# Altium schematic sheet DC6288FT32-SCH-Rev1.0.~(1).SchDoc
size A4
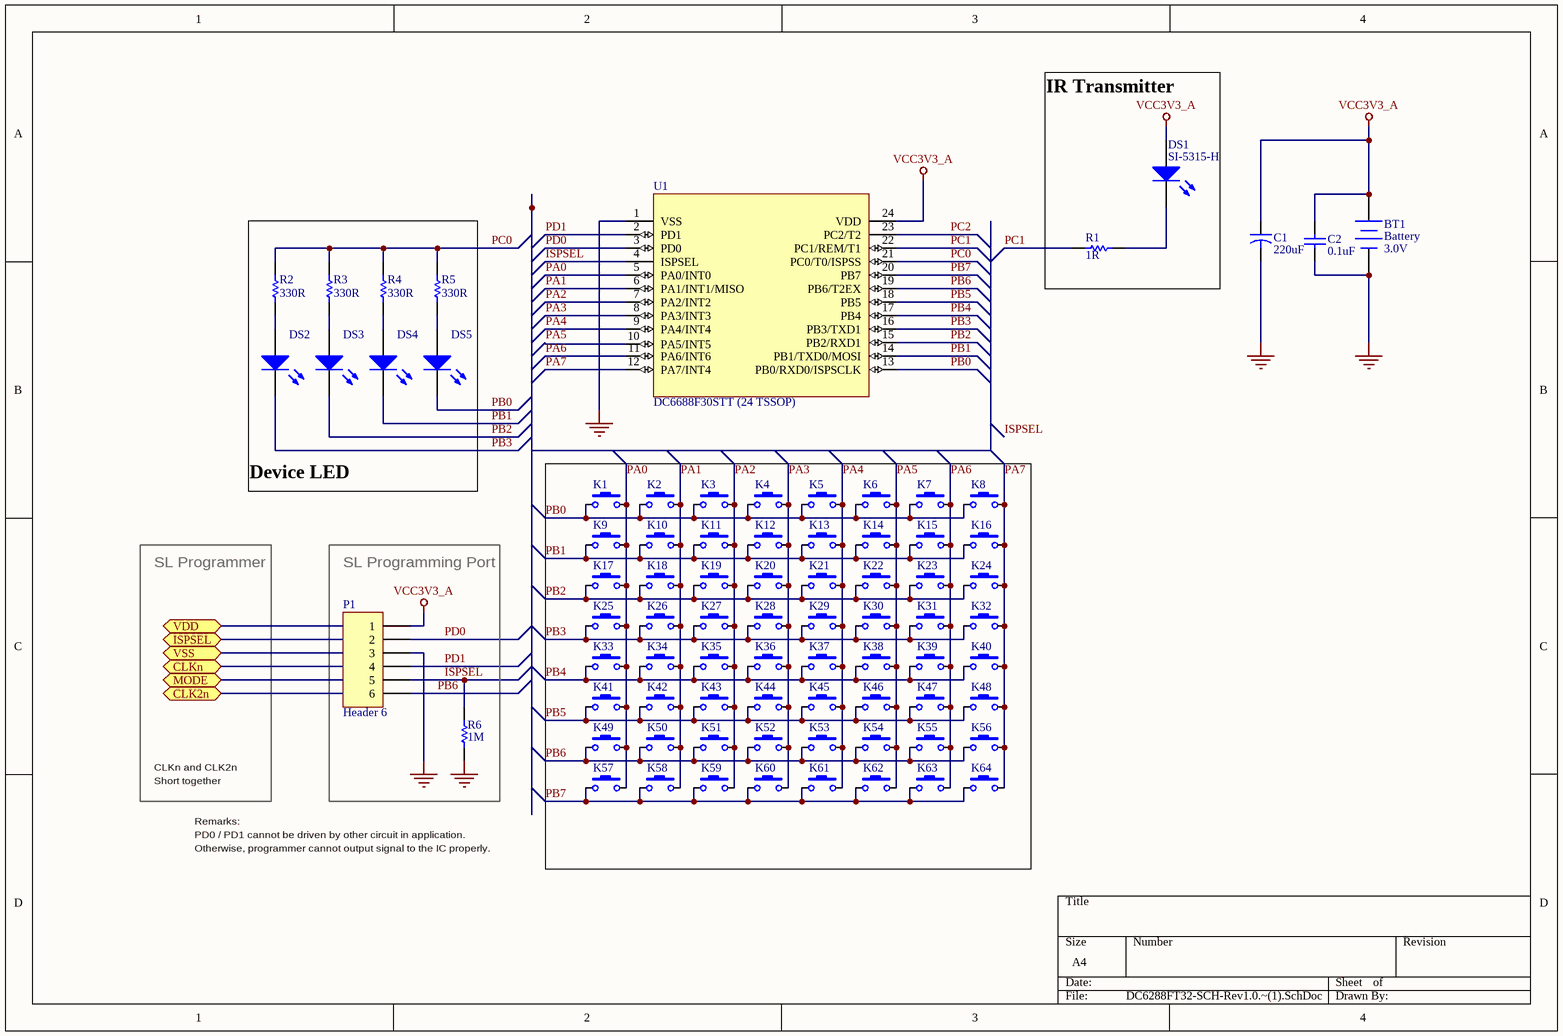
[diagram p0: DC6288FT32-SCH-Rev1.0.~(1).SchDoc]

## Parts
BT1  Battery  value 3.0V  [BAT-2]
C1  value 220uF  [CAPR5-4X5]  (hidden comment: Cap2)
C2  value 0.1uF  [RAD-0.3]  (hidden comment: Cap)
DS1  SPEC: SI-5315-H  [LED-0]  (hidden comment: LED0)
DS2  LED1  [LED-1]  (value not drawn)
DS3  LED1  [LED-1]  (value not drawn)
DS4  LED1  [LED-1]  (value not drawn)
DS5  LED1  [LED-1]  (value not drawn)
K1  KEYPAD_SW  [DPST-4]  (value not drawn)
K2  KEYPAD_SW  [DPST-4]  (value not drawn)
K3  KEYPAD_SW  [DPST-4]  (value not drawn)
K4  KEYPAD_SW  [DPST-4]  (value not drawn)
K5  KEYPAD_SW  [DPST-4]  (value not drawn)
K6  KEYPAD_SW  [DPST-4]  (value not drawn)
K7  KEYPAD_SW  [DPST-4]  (value not drawn)
K8  KEYPAD_SW  [DPST-4]  (value not drawn)
K9  KEYPAD_SW  [DPST-4]  (value not drawn)
K10  KEYPAD_SW  [DPST-4]  (value not drawn)
K11  KEYPAD_SW  [DPST-4]  (value not drawn)
K12  KEYPAD_SW  [DPST-4]  (value not drawn)
K13  KEYPAD_SW  [DPST-4]  (value not drawn)
K14  KEYPAD_SW  [DPST-4]  (value not drawn)
K15  KEYPAD_SW  [DPST-4]  (value not drawn)
K16  KEYPAD_SW  [DPST-4]  (value not drawn)
K17  KEYPAD_SW  [DPST-4]  (value not drawn)
K18  KEYPAD_SW  [DPST-4]  (value not drawn)
K19  KEYPAD_SW  [DPST-4]  (value not drawn)
K20  KEYPAD_SW  [DPST-4]  (value not drawn)
K21  KEYPAD_SW  [DPST-4]  (value not drawn)
K22  KEYPAD_SW  [DPST-4]  (value not drawn)
K23  KEYPAD_SW  [DPST-4]  (value not drawn)
K24  KEYPAD_SW  [DPST-4]  (value not drawn)
K25  KEYPAD_SW  [DPST-4]  (value not drawn)
K26  KEYPAD_SW  [DPST-4]  (value not drawn)
K27  KEYPAD_SW  [DPST-4]  (value not drawn)
K28  KEYPAD_SW  [DPST-4]  (value not drawn)
K29  KEYPAD_SW  [DPST-4]  (value not drawn)
K30  KEYPAD_SW  [DPST-4]  (value not drawn)
K31  KEYPAD_SW  [DPST-4]  (value not drawn)
K32  KEYPAD_SW  [DPST-4]  (value not drawn)
K33  KEYPAD_SW  [DPST-4]  (value not drawn)
K34  KEYPAD_SW  [DPST-4]  (value not drawn)
K35  KEYPAD_SW  [DPST-4]  (value not drawn)
K36  KEYPAD_SW  [DPST-4]  (value not drawn)
K37  KEYPAD_SW  [DPST-4]  (value not drawn)
K38  KEYPAD_SW  [DPST-4]  (value not drawn)
K39  KEYPAD_SW  [DPST-4]  (value not drawn)
K40  KEYPAD_SW  [DPST-4]  (value not drawn)
K41  KEYPAD_SW  [DPST-4]  (value not drawn)
K42  KEYPAD_SW  [DPST-4]  (value not drawn)
K43  KEYPAD_SW  [DPST-4]  (value not drawn)
K44  KEYPAD_SW  [DPST-4]  (value not drawn)
K45  KEYPAD_SW  [DPST-4]  (value not drawn)
K46  KEYPAD_SW  [DPST-4]  (value not drawn)
K47  KEYPAD_SW  [DPST-4]  (value not drawn)
K48  KEYPAD_SW  [DPST-4]  (value not drawn)
K49  KEYPAD_SW  [DPST-4]  (value not drawn)
K50  KEYPAD_SW  [DPST-4]  (value not drawn)
K51  KEYPAD_SW  [DPST-4]  (value not drawn)
K52  KEYPAD_SW  [DPST-4]  (value not drawn)
K53  KEYPAD_SW  [DPST-4]  (value not drawn)
K54  KEYPAD_SW  [DPST-4]  (value not drawn)
K55  KEYPAD_SW  [DPST-4]  (value not drawn)
K56  KEYPAD_SW  [DPST-4]  (value not drawn)
K57  KEYPAD_SW  [DPST-4]  (value not drawn)
K58  KEYPAD_SW  [DPST-4]  (value not drawn)
K59  KEYPAD_SW  [DPST-4]  (value not drawn)
K60  KEYPAD_SW  [DPST-4]  (value not drawn)
K61  KEYPAD_SW  [DPST-4]  (value not drawn)
K62  KEYPAD_SW  [DPST-4]  (value not drawn)
K63  KEYPAD_SW  [DPST-4]  (value not drawn)
K64  KEYPAD_SW  [DPST-4]  (value not drawn)
P1  Header 6  [HDR1X6]
R1  value 1R  [AXIAL-0.3]  (hidden comment: Res1)
R2  value 330R  [AXIAL-0.3]  (hidden comment: Res1)
R3  value 330R  [AXIAL-0.3]  (hidden comment: Res1)
R4  value 330R  [AXIAL-0.3]  (hidden comment: Res1)
R5  value 330R  [AXIAL-0.3]  (hidden comment: Res1)
R6  value 1M  [AXIAL-0.3]  (hidden comment: Res1)
U1  DC6688F30STT (24 TSSOP)

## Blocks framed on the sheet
SL Programming Port: P1 R6

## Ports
CLK2n, CLKn, ISPSEL, MODE, VDD, VSS

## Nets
GND: BT1.2(-) C1.2 C2.1 P1.3 R6.1 U1.1(VSS)
VCC3V3_A: BT1.1(+) C1.1 C2.2 DS1.1(A) P1.1 U1.24(VDD)
ISPSEL: P1.5 R6.2 U1.4(ISPSEL)
PA0: K1.2 K9.2 K17.2 K25.2 K33.2 K41.2 K49.2 K57.2 U1.5(PA0/INT0)
PA1: K2.2 K10.2 K18.2 K26.2 K34.2 K42.2 K50.2 K58.2 U1.6(PA1/INT1/MISO)
PA2: K3.2 K11.2 K19.2 K27.2 K35.2 K43.2 K51.2 K59.2 U1.7(PA2/INT2)
PA3: K4.2 K12.2 K20.2 K28.2 K36.2 K44.2 K52.2 K60.2 U1.8(PA3/INT3)
PA4: K5.2 K13.2 K21.2 K29.2 K37.2 K45.2 K53.2 K61.2 U1.9(PA4/INT4)
PA5: K6.2 K14.2 K22.2 K30.2 K38.2 K46.2 K54.2 K62.2
PA6: K7.2 K15.2 K23.2 K31.2 K39.2 K47.2 K55.2 K63.2 U1.11(PA6/INT6)
PA7: K8.2 K16.2 K24.2 K32.2 K40.2 K48.2 K56.2 K64.2 U1.12(PA7/INT4)
PB0: DS5.2(K) K1.1 K2.1 K3.1 K4.1 K5.1 K6.1 K7.1 K8.1 U1.13(PB0/RXD0/ISPSCLK)
PB1: DS4.2(K) K9.1 K10.1 K11.1 K12.1 K13.1 K14.1 K15.1 K16.1 U1.14(PB1/TXD0/MOSI)
PB2: DS3.2(K) K17.1 K18.1 K19.1 K20.1 K21.1 K22.1 K23.1 K24.1 U1.15(PB2/RXD1)
PB3: DS2.2(K) K25.1 K26.1 K27.1 K28.1 K29.1 K30.1 K31.1 K32.1 U1.16(PB3/TXD1)
PB4: K33.1 K34.1 K35.1 K36.1 K37.1 K38.1 K39.1 K40.1 U1.17(PB4)
PB5: K41.1 K42.1 K43.1 K44.1 K45.1 K46.1 K47.1 K48.1 U1.18(PB5)
PB6: K49.1 K50.1 K51.1 K52.1 K53.1 K54.1 K55.1 K56.1 P1.6 U1.19(PB6/T2EX)
PB7: K57.1 K58.1 K59.1 K60.1 K61.1 K62.1 K63.1 K64.1 U1.20(PB7)
PC0: R2.2 R3.2 R4.2 R5.2 U1.21(PC0/T0/ISPSS)
PC1: R1.1 U1.22(PC1/REM/T1)
PC2: U1.23(PC2/T2)
PD0: P1.2 U1.3(PD0)
PD1: P1.4 U1.2(PD1)
NetDS1_2: DS1.2(K) R1.2
NetDS2_1: DS2.1(A) R2.1
NetDS3_1: DS3.1(A) R3.1
NetDS4_1: DS4.1(A) R4.1
NetDS5_1: DS5.1(A) R5.1

Not connected (* = marked no-connect by the designer): U1 10(PA5/INT5)

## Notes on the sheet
- IR Transmitter
- Device LED
- SL Programmer
- CLKn and CLK2n
- Short together
- Remarks:
- PD0 / PD1 cannot be driven by other circuit in application.
- Otherwise, programmer cannot output signal to the IC properly.
- Keypad
- Labels drawn without touching a wire or pin: ISPSEL, PA5

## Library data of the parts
BT1 = Battery: Multicell Battery; Manufacturer: Generic Components
C1 = Cap2: Capacitor; Manufacturer: Generic Components; Class I: Passive
C2 = Cap: Capacitor; Manufacturer: Generic Components; Class I: Passive
DS1 = LED0: Typical INFRARED GaAs LED; Manufacturer: Generic Components; Class I: Optoelectronic
DS2-DS5 = LED1: Typical RED GaAs LED; Manufacturer: Generic Components; Class I: Optoelectronic
P1 = Header 6: Header, 6-Pin
R1-R6 = Res1: Resistor; Manufacturer: Generic Components; Class I: Passive
U1 = DC6688FST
